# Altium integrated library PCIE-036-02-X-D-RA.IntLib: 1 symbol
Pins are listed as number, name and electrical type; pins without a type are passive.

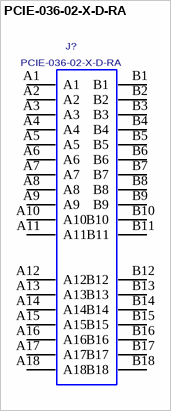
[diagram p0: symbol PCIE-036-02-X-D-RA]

## PCIE-036-02-X-D-RA
designator J?
PCI EXPRESS RIGHT ANGLE ASSEMBLY, 36 PINS.; MANUFACTURER: SAMTEC
footprint PCIE-036-02-X-D-RA
pins: A1, A2, A3, A4, A5, A6, A7, A8, A9, A10, A11, A12, A13, A14, A15, A16, A17, A18, B1, B2, B3, B4, B5, B6, B7, B8, B9, B10, B11, B12, B13, B14, B15, B16, B17, B18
